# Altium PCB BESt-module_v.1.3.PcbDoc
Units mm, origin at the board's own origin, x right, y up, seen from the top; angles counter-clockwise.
Board outline 26.5 x 50.5 mm, 2 copper layers (Top, Bottom); 61 components, 102 nets, 346 pads, 158 vias.
Unrouted connection lines stored in the file: 17.
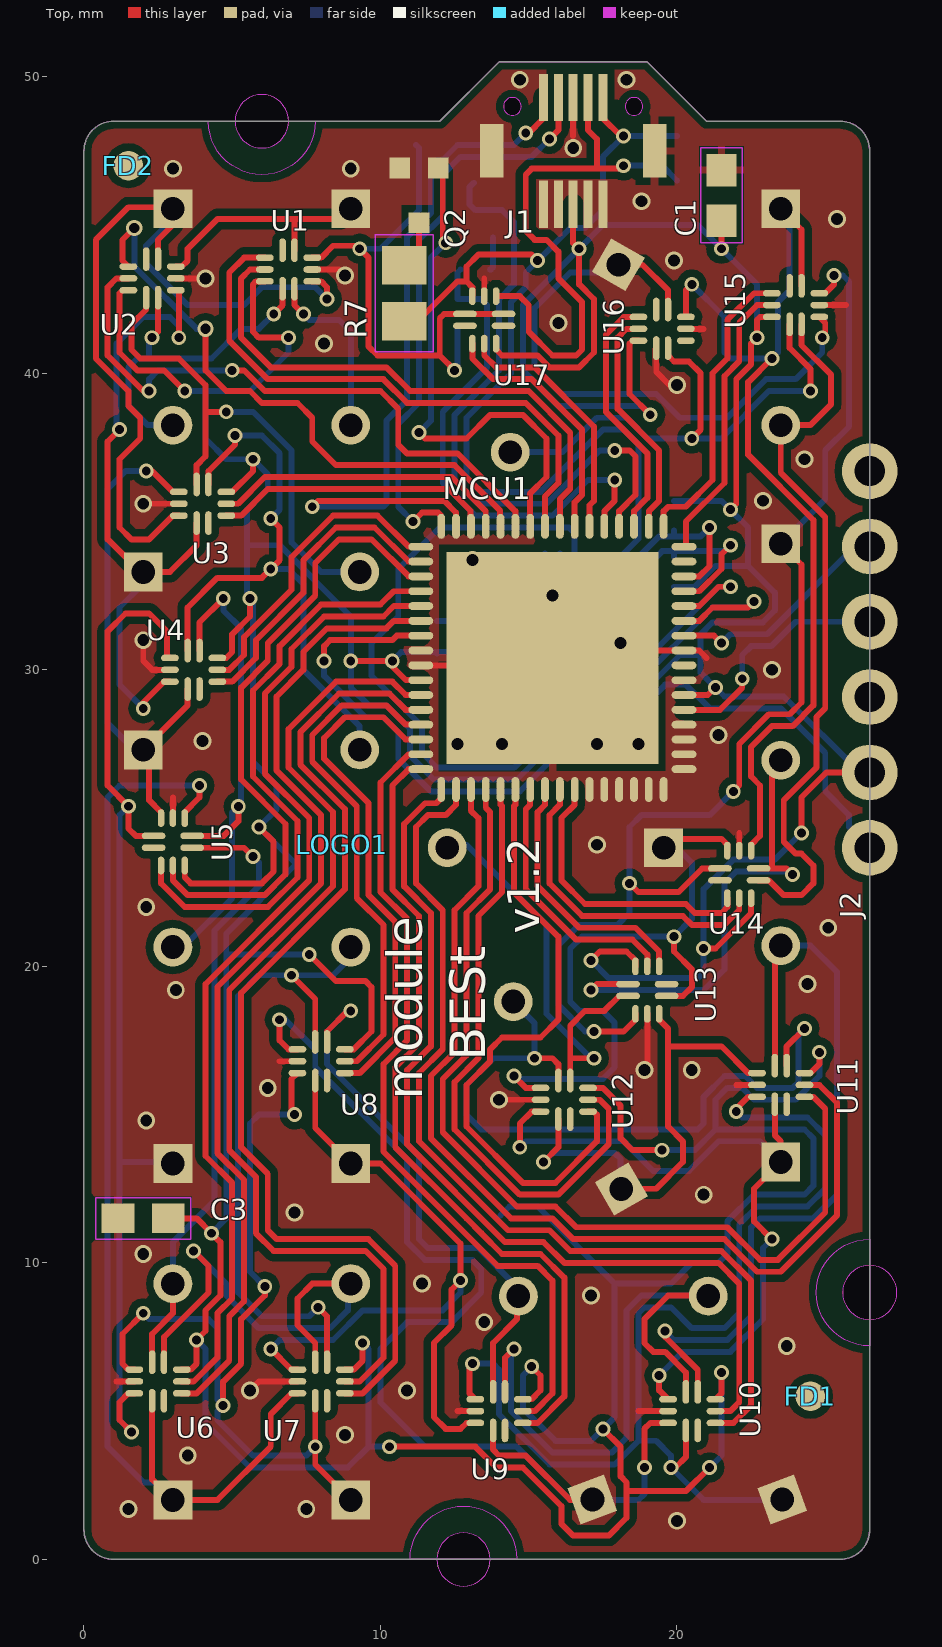
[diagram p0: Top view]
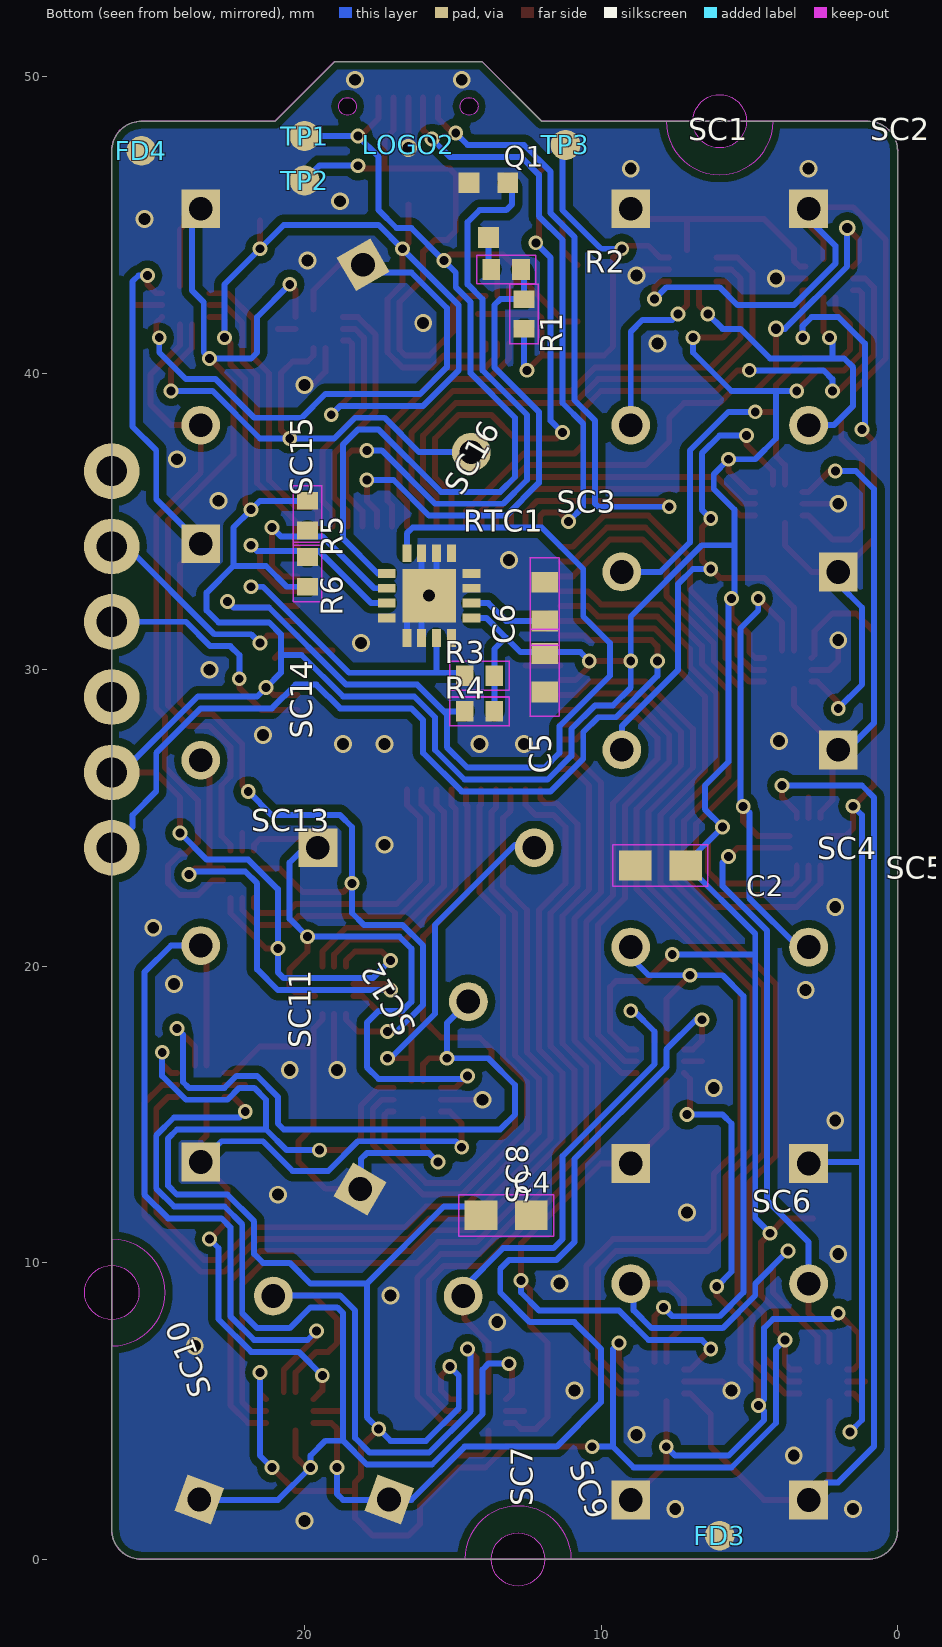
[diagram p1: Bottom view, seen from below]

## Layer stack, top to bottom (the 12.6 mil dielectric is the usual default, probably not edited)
Top Solder: solder mask 0.0102, Solder Resist, Dk 3.5
Top: signal copper 0.035
Dielectric 1: dielectric 0.32, FR-4, Dk 4.8
Bottom: signal copper 0.035
Bottom Solder: solder mask 0.0102, Solder Resist, Dk 3.5

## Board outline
19,50.5 21,48.5 25.5,48.5 cw(c25.5,47.5) 26.5,47.5 26.5,1 cw(c25.5,1) 25.5,0 1,0 cw(c1,1) 0,1 0,47.5 cw(c1,47.5) 1,48.5 12,48.5 14,50.5
cut-out: 26.5,8.085 ccw(c26.5,9) 27.415,9 ccw(c26.5,9) 26.5,9.915 ccw(c26.5,9) 25.585,9 ccw(c26.5,9)
cut-out: 12.8,-0.9 ccw(c12.8,0) 13.7,0 ccw(c12.8,0) 12.8,0.9 ccw(c12.8,0) 11.9,0 ccw(c12.8,0)
cut-out: 6,47.6 ccw(c6,48.5) 6.9,48.5 ccw(c6,48.5) 6,49.4 ccw(c6,48.5) 5.1,48.5 ccw(c6,48.5)
cut-out: 18.55,48.7 ccw(c18.55,49) 18.85,49 ccw(c18.55,49) 18.55,49.3 ccw(c18.55,49) 18.25,49 ccw(c18.55,49)
cut-out: 14.45,48.7 ccw(c14.45,49) 14.75,49 ccw(c14.45,49) 14.45,49.3 ccw(c14.45,49) 14.15,49 ccw(c14.45,49)

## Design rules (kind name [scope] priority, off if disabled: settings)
BoardOutlineClearance mdCopperDimension [All] p1: gap=0.254 ignorepadtopadclearanceinfootprint=FALSE except(0: Arc-SplitContinuation Track-SplitContinuation SMDPad-SplitContinuation THPad-SplitContinuation Via-SplitContinuation Fill-SplitContinuation Poly-SplitContinuation Region-SplitContinuation Text-SplitContinuation; 0.152: Poly-OutlineEdge Poly-CavityEdge Poly-CutoutEdge Poly-SplitBarrior)
Clearance Clearance_for_PolygonClass_Isolate_10 [InPolygonClass('Isolate_10') vs IsArc Or IsTrack Or IsPad Or IsVia Or IsFill Or IsRegion Or IsText] p1: gap=0.254 ignorepadtopadclearanceinfootprint=FALSE
Clearance "Clearance (Same Net)" [All] p2: gap=0.152 ignorepadtopadclearanceinfootprint=FALSE
Clearance [All] p3: gap=0.152 ignorepadtopadclearanceinfootprint=FALSE
HoleSize [All] p1: absolutevalues=TRUE maxlimit=2540 minlimit=0.3 maxpercent=80.000 minpercent=20.000
HoleToHoleClearance mdDrill [All] p1: gap=0.152 allowstackedmicrovias=TRUE
MinimumSolderMaskSliver [All] p1 off: minsoldermaskwidth=0.254
PasteMaskExpansion Expansion_SMDPaste_OFF [InPadClass('SMDPaste_OFF')] p1: expansion=0
PasteMaskExpansion mlMinCreamFrame [All] p2: expansion=0
PolygonConnect PolygonConnect_For_PolygonThermal_ON_Width100000_Gap100000 [InPolygonClass('PolygonThermal_ON_Width100000_Gap100000') vs Not IsVia] p1: connectstyle=Relief reliefconductorwidth=0.254 reliefentries=4 polygonreliefangle="90 Angle" airgapwidth=0.254
PolygonConnect ThermalVias [IsVia] p2: connectstyle=Direct reliefconductorwidth=0.254 reliefentries=4 polygonreliefangle="90 Angle" airgapwidth=0.254
PolygonConnect [All] p3: connectstyle=Relief reliefconductorwidth=0.254 reliefentries=4 polygonreliefangle="90 Angle" airgapwidth=0.254
RoutingVias [All] p1: holewidth=0.3 width=0.5 viastyle="Through Hole" minholewidth=0.3 minwidth=0.5 maxholewidth=2.54 maxwidth=2.54
SolderMaskExpansion mlMinStopFrame [All] p1: expansion=0.102 istentingtop=FALSE
Width [All] p1: maxlimit=0.254 minlimit=0.152 preferedwidth=0.152
26 further rules are at their usual default settings.

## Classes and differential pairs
polygon class PolygonThermal_ON_Width100000_Gap100000: Polygon_1_Net_GND Polygon_2_Net_GND
polygon class Isolate_10: Polygon_1_Net_GND Polygon_2_Net_GND
pad class SMDPaste_OFF: FD1-1 FD2-1 FD3-1 FD4-1 TP1-P$1 TP2-P$1 TP3-P$1

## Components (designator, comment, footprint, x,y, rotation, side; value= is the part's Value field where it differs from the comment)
C1 "" 0603 21.5,46 r270 top
C2 "" 0603 8,23.4 r180 bottom
C3 "" 0603 2,11.5 r0 top
C4 "" 0603 13.2,11.6 r0 bottom
C5 "" C0402 11.9,29.9 r270 bottom
C6 "" C0402 11.9,32.3 r90 bottom
FD1 "" FIDUCIAL-1X2 24.5,5.5 r0 top
FD2 "" FIDUCIAL-1X2 1.5,47 r0 top
FD3 "" FIDUCIAL-1X2 6,0.8 r180 bottom
FD4 "" FIDUCIAL-1X2 25.5,47.5 r180 bottom
J1 "" 10132797-10POS-PLUG 16.5,47.5 r0 top
J2 "" 1X06_NO_SILK 26.5,24 r90 top
LOGO1 "" IIOT 8.7,24.1 r90 top
LOGO2 "" IIOT 16.5,47.7 r90 bottom
MCU1 "" QFN50P900X900X100-65T715N 15.8,30.4 r0 top
Q1 "" SOT323 13.8,45.5 r0 bottom
Q2 "" SOT323 11.3,46 r180 top
R1 "" R0402 12.6,42 r270 bottom
R2 "" R0402 13.2,43.5 r180 bottom
R3 "" R0402 14.1,29.8 r0 bottom
R4 "" R0402 14.1,28.6 r0 bottom
R5 "" R0402 19.9,35.2 r270 bottom
R6 "" R0402 19.9,33.3 r90 bottom
R7 "" R0805 10.8,42.7 r270 top
RTC1 "" QFN-16-3X3 15.8,32.5 r270 bottom
SC1 "" EATON-13X11.3X6-V 9,41.9 r0 bottom
SC2 "" EATON-13X11.3X6-V 3,41.9 r0 bottom
SC3 "" EATON-13X11.3X6-V 5.65,33.3 r90 bottom
SC4 "" EATON-13X11.3X6-V 5.65,27.3 r90 bottom
SC5 "" EATON-13X11.3X6-V 3,17 r180 bottom
SC6 "" EATON-13X11.3X6-V 3,5.65 r180 bottom
SC7 "" EATON-13X11.3X6-V 9,5.65 r180 bottom
SC8 "" EATON-13X11.3X6-V 9,17 r180 bottom
SC9 "" EATON-13X11.3X6-V 15.9,5.45 r200 bottom
SC10 "" EATON-13X11.3X6-V 22.3,5.45 r200 bottom
SC11 "" EATON-13X11.3X6-V 23.5,17.05 r180 bottom
SC12 "" EATON-13X11.3X6-V 16.3,15.65 r210 bottom
SC13 "" EATON-13X11.3X6-V 15.9,24 r270 bottom
SC14 "" EATON-13X11.3X6-V 23.5,30.6 r0 bottom
SC15 "" EATON-13X11.3X6-V 23.5,41.9 r0 bottom
SC16 "" EATON-13X11.3X6-V 16.2,40.5 r330 bottom
TP1 "" PAD.03X.04 20,48 r180 bottom
TP2 "" PAD.03X.04 20,46.5 r180 bottom
TP3 "" PAD.03X.04 11.2,47.7 r180 bottom
U1 "" CP-10-10 6.9,43.5 r270 top
U2 "" CP-10-10 2.3,43.2 r270 top
U3 "" CP-10-10 4,35.6 r90 top
U4 "" CP-10-10 3.7,30 r90 top
U5 "" CP-10-10 3,24.2 r0 top
U6 "" CP-10-10 2.5,6 r90 top
U7 "" CP-10-10 8,6 r90 top
U8 "" CP-10-10 8,16.8 r90 top
U9 "" CP-10-10 14,5 r90 top
U10 "" CP-10-10 20.5,5 r90 top
U11 "" CP-10-10 23.5,16 r90 top
U12 "" CP-10-10 16.2,15.5 r90 top
U13 "" CP-10-10 19,19.2 r180 top
U14 "" CP-10-10 22.1,23.1 r0 top
U15 "" CP-10-10 24,42.3 r270 top
U16 "" CP-10-10 19.5,41.5 r270 top
U17 "" CP-10-10 13.5,41.8 r0 top

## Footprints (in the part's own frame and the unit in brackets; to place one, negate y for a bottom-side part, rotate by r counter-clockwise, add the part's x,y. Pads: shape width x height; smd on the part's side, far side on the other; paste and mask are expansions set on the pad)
1X06_NO_SILK [mil] "1X06_NO_SILK"
  round 74 hole 40: 1(0,0) 2(100,0) 3(200,0) 4(300,0) 5(400,0) 6(500,0)
0603 [mm] "0603"
  rect 1.1x1 smd: 1(-0.85,0) 2(0.85,0)
  Top keep-out lines w0.051: 1.6,-0.7 -1.6,-0.7 -1.6,0.7 1.6,0.7 1.6,-0.7
10132797-10POS-PLUG [mm] "10132797-10POS-PLUG"
  rect 0.3x1.6 smd: 1(1,1.8) 2(0.5,1.8) 3(0,1.8) 4(-0.5,1.8) 5(-1,1.8) 6(-1,-1.8) 7(-0.5,-1.8) 8(0,-1.8) 9(0.5,-1.8) 10(1,-1.8)
  rect 0.8x1.8 smd: MNT1(-2.75,0) MNT2(2.75,0)
C0402 [mm] "C0402"
  rect 0.7x0.9 smd: 1(-0.65,0) 2(0.65,0)
  Top keep-out lines w0.051: 1.473,0.483 1.473,-0.483 -1.473,-0.483 -1.473,0.483 1.473,0.483
CP-10-10 [mil] "CP-10-10"
  rrect100% 8.66x23.62 smd: 1(-15.75,31.5) 4(-15.75,-31.5) 5(0,-31.5) 6(15.75,-31.5) 9(15.75,31.5) 10(0,31.5)
  rrect100% 31.5x8.66 smd: 2(-25.59,7.87) 3(-25.59,-7.87) 7(25.59,-7.87) 8(25.59,7.87)
EATON-13X11.3X6-V [mil] "EATON-13X11.3X6-V"
  round 51.5 hole 31.5: N(0,143.7)
  rect 51.5x51.5 / inner round 47.58 / far side rect 51.5x51.5 hole 31.5: P(0,-143.7)
FIDUCIAL-1X2 [mm] "FIDUCIAL-1X2"
  rrect100% 1x1 smd paste+0: 1(0,0)
IIOT [mm] "IIOT"
PAD.03X.04 [mil] "PAD.03X.04"
  rrect100% 40x40 smd paste+0: P$1(0,0)
QFN50P900X900X100-65T715N [mil] "QFN50P900X900X100-65T715N"
  rrect100% 32.96x10.39 smd: 1(-174.7,147.64) 2(-174.7,127.95) 3(-174.7,108.27) 4(-174.7,88.58) 5(-174.7,68.9) 6(-174.7,49.21) 7(-174.7,29.53) 8(-174.7,9.84) 9(-174.7,-9.84) 10(-174.7,-29.53) 11(-174.7,-49.21) 12(-174.7,-68.9) 13(-174.7,-88.58) 14(-174.7,-108.27) 15(-174.7,-127.95) 16(-174.7,-147.64) 33(174.7,-147.64) 34(174.7,-127.95) 35(174.7,-108.27) 36(174.7,-88.58) 37(174.7,-68.9) 38(174.7,-49.21) 39(174.7,-29.53) 40(174.7,-9.84) 41(174.7,9.84) 42(174.7,29.53) 43(174.7,49.21) 44(174.7,68.9) 45(174.7,88.58) 46(174.7,108.27) 47(174.7,127.95) 48(174.7,147.64)
  rrect100% 10.39x32.96 smd: 17(-147.64,-174.7) 18(-127.95,-174.7) 19(-108.27,-174.7) 20(-88.58,-174.7) 21(-68.9,-174.7) 22(-49.21,-174.7) 23(-29.53,-174.7) 24(-9.84,-174.7) 25(9.84,-174.7) 26(29.53,-174.7) 27(49.21,-174.7) 28(68.9,-174.7) 29(88.58,-174.7) 30(108.27,-174.7) 31(127.95,-174.7) 32(147.64,-174.7) 49(147.64,174.7) 50(127.95,174.7) 51(108.27,174.7) 52(88.58,174.7) 53(68.9,174.7) 54(49.21,174.7) 55(29.53,174.7) 56(9.84,174.7) 57(-9.84,174.7) 58(-29.53,174.7) 59(-49.21,174.7) 60(-68.9,174.7) 61(-88.58,174.7) 62(-108.27,174.7) 63(-127.95,174.7) 64(-147.64,174.7)
  rect 281.5x281.5 smd: 65(0,0)
QFN-16-3X3 [mm] "QFN-16-3X3"
  rect 0.6x0.3 smd: 1(-1.43,0.75) 2(-1.43,0.25) 3(-1.43,-0.25) 4(-1.43,-0.75) 9(1.43,-0.75) 10(1.43,-0.25) 11(1.43,0.25) 12(1.43,0.75)
  rect 0.3x0.6 smd: 5(-0.75,-1.43) 6(-0.25,-1.43) 7(0.25,-1.43) 8(0.75,-1.43) 13(0.75,1.43) 14(0.25,1.43) 15(-0.25,1.43) 16(-0.75,1.43)
  rect 1.8x1.8 smd: EP(0,0)
R0402 [mm] "R0402"
  rect 0.6x0.7 smd: 1(-0.5,0) 2(0.5,0)
  Top keep-out lines w0.051: 1,0.483 1,-0.483 -1,-0.483 -1,0.483 1,0.483
R0805 [mm] "R0805"
  rect 1.3x1.5 smd: 1(-0.95,0) 2(0.95,0)
  Top keep-out lines w0.051: 1.973,-0.983 -1.973,-0.983 -1.973,0.983 1.973,0.983 1.973,-0.983
SOT323 [mm] "SOT323"
  rect 0.7x0.7 smd: 1(-0.65,-0.925) 2(0.65,-0.925) 3(0,0.925)

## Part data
C1 C2 C3 C4: library part 0603
C5 C6: library part C0402
FD1 FD2 FD3 FD4: library part FIDUCIAL-1X2
J1: library part 10132797-10POS-PLUG
J2: library part 1X06_NO_SILK
LOGO1 LOGO2: library part IIOT
MCU1: library part QFN50P900X900X100-65T715N
Q1 Q2: library part SOT323
R1 R2 R3 R4 R5 R6: library part R0402
R7: library part R0805
RTC1: library part QFN-16-3X3
SC1 SC2 SC3 SC4 SC5 SC6 SC7 SC8 SC9 SC10 SC11 SC12 SC13 SC14 SC15 SC16: library part EATON-13X11.3X6-V
TP1 TP2 TP3: library part PAD.03X.04
U1 U2 U3 U4 U5 U6 U7 U8 U9 U10 U11 U12 U13 U14 U15 U16 U17: library part CP-10-10

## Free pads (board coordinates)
  round 1.8 hole 1.8 unplated: MH1(6,48.5) MH3(12.8,0)
  round 0.6 hole 0.6 unplated: MH1(14.45,49) MH2(18.55,49)
  round 1.83 hole 1.83 unplated: MH2(26.5,9)

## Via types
v1: diameter 0.5/0.5 (per signal layer), hole 0.3, Top to Bottom, 105 vias
v2: diameter 0.6/0.6 (per signal layer), hole 0.4, Top to Bottom, 51 vias
v3: diameter 0.55/0.55 (per signal layer), hole 0.35, Top to Bottom, 2 vias

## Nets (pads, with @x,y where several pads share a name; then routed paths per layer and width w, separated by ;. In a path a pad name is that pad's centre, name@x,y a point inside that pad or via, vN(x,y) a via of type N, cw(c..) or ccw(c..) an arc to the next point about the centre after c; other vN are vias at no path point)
ADC: MCU1.53 R1.1 R2.2 | length 17.2
  Top w0.2: MCU1.53@17.55,34.837 17.55,35.35 17.9,35.7 v1(17.9,36.4)
  Bottom w0.2: R2.2 12.6,43.4 R1.1 13.4,42.5 13.6,42.3 13.6,40.198 12.1,38.698 12.1,36.303 13.203,35.2 15.8,35.2 17,36.4 v1(17.9,36.4)
C1-N: SC1.N U1.8 | length 6
  Top w0.2: U1.8 7.1,42.3 v1(7.4,42)
  Bottom w0.2: v1(7.4,42) 7.6,41.8 8.6,41.8 9,41.4 SC1.N
C1-N-SW: MCU1.56 U1.5 | length 18.7
  Top w0.2: U1.5 5.6,43.5 5.3,43.2 5.3,41.2 6.3,40.2 10.2,40.2 11,39.4 15,39.4 16.4,38 16.4,36.102 16.05,35.752 MCU1.56
C1-NC: U1.3
C1-P: SC1.P U1.2 U2.1 | length 8
  Top w0.2: U2.1 3.3,43.6 3.5,43.8 3.5,44.2 4.5,45.2 7.1,45.2 ; U1.2 7.1,45.2 ; SC1.P 8.65,45.2 7.1,45.2
C1-P-SW: MCU1.57 U1.4 | length 19.4
  Top w0.2: U1.4 5.402,43.9 4.9,43.398 4.9,41.1 6.2,39.8 10.1,39.8 10.9,39 14.9,39 16,37.9 16,36.3 15.55,35.85 MCU1.57
C2-N: SC2.N U1.7 U2.8 | length 11.9
  Top w0.2: v1(2.3,41.2) 2.5,41.4 U2.8 ; v1(6.4,42) 6.7,42.3 U1.7
  Bottom w0.2: v1(2.3,41.2) 2.2,41.1 2.2,40.5 ; SC2.N 2.15,38.25 1.5,38.9 1.5,40.2 1.8,40.5 2.2,40.5 ; v1(6.4,42) 5.9,41.5 5.3,41.5 4.3,40.5 2.2,40.5
C2-N-SW: MCU1.59 U2.5 | length 21.1
  Top w0.2: U2.5@1.5,43.2 1.1,43.2 0.8,42.9 0.8,40.6 2,39.4 v1(2.2,39.4) ; v1(5,40.1) 5.4,40.1 6.1,39.4 10,39.4 10.6,38.8 10.6,37.589 10.889,37.3 12.6,37.3 14.55,35.35 MCU1.59
  Bottom w0.2: v1(2.2,39.4) 2.2,39.8 2.5,40.1 v1(5,40.1)
C2-NC: U2.3
C2-P: SC2.P U1.9 U2.2 U3.1 | length 28.4
  Top w0.2: U2.2 2.5,44.5 3,45 SC2.P 3,45.6 1.5,45.6 0.4,44.5 0.4,40.5 1.5,39.4 1.5,38.9 1.9,38.5 1.9,37.8 1.2,37.1 1.2,34.8 1.6,34.4 2.2,34.4 3,35.2 U3.1 ; U1.9 8,43.1 8.2,42.9 v1(8.2,42.5)
  Bottom w0.2: SC2.P 3,45.2 2.1,44.3 2.1,43.698 3.498,42.3 5.4,42.3 6,42.9 7.8,42.9 v1(8.2,42.5)
C2-P-SW: MCU1.60 U2.4 | length 20.4
  Top w0.2: U2.4@1.5,43.6 1.3,43.8 1.3,44.5 v3(1.7,44.9) ; v3(4.1,41.5) 4.1,40.1 4.8,39.4 5.6,39.4 ; 5.602,39.4 5.6,39.4 ; MCU1.60 14.035,34.853 14.035,35.364 12.498,36.9 8.5,36.9 7.7,37.7 7.7,38.5 7.2,39 6,39 5.6,39.4
  Bottom w0.2: v3(1.7,44.9) 1.7,43.6 3.8,41.5 v3(4.1,41.5)
C3-N: SC3.N U2.7 U3.8 | length 17.7
  Top w0.2: U2.7 2.1,42.15 1.6,41.65 1.6,40.8 1.9,40.5 3.2,40.5 4.1,39.6 4.1,38.7 ; U3.8 3.8,36.9 4.1,37.2 4.1,38.7 ; v1(4.8,38.7) 4.1,38.7
  Bottom w0.2: v1(4.8,38.7) 5.7,38.7 7,37.4 7,34.3 8,33.3 SC3.N
C3-N-SW: MCU1.61 U3.5 | length 10.1
  Top w0.2: U3.5 5.2,35.6 6.1,36.5 12.4,36.5 13.55,35.35 MCU1.61
C3-NC: U3.3
C3-P: SC3.P U2.9 U3.2 U4.1 | length 22.7
  Top w0.2: v1(1.2,38.1) 0.8,37.7 0.8,34.4 1.9,33.3 SC3.P 2.9,33.3 3.8,34.2 U3.2 ; v1(2,28.7) 2,28.9 2.7,29.6 U4.1 ; U2.9 3.2,42.8 v1(3.2,41.2)
  Bottom w0.2: v1(1.2,38.1) 1.1,38.2 1.1,41 2,41.9 2.9,41.9 3.2,41.6 v1(3.2,41.2) ; v1(2,28.7) 1.2,29.5 1.2,32.1 2,32.9 SC3.P
C3-P-SW: MCU1.62 U3.4 | length 9.4
  Top w0.2: U3.4 5.3,35.2 6.2,36.1 12.298,36.1 13.035,35.364 13.035,34.853 MCU1.62
C4-N: SC4.N U3.7 U4.8 | length 20.5
  Top w0.2: U4.8 3.5,32.1 4.5,33.1 6,33.1 v1(6.3,33.4) 6.6,33.7 6.6,34.8 v1(6.3,35.1) ; U3.7 4.2,36.7 5.1,37.6 v1(5.1,37.9)
  Bottom w0.2: v1(5.1,37.9) 6,37.9 6.6,37.3 6.6,35.4 v1(6.3,35.1) ; v1(6.3,33.4) 6.9,33.4 7.4,32.9 7.4,30 9.3,28.1 SC4.N
C4-N-SW: MCU1.1 U4.5 | length 10.4
  Top w0.2: U4.5 4.9,30 5.4,30.5 5.4,31.1 7,32.7 7,33.8 8.4,35.2 9.9,35.2 10.95,34.15 MCU1.1
C4-NC: U4.3
C4-P: SC4.P U3.9 U4.2 U5.1 | length 17.6
  Top w0.2: v1(2.1,36.7) 2.3,36.7 3,36 U3.9 ; U5.1@2.6,25 2.6,25.2 2.2,25.6 2.2,27.1 SC4.P 3.5,28.8 U4.2
  Bottom w0.2: SC4.P 1.7,27.3 0.8,28.2 0.8,36.1 1.4,36.7 v1(2.1,36.7)
C4-P-SW: MCU1.2 U4.4 | length 10.5
  Top w0.2: U4.4 5,29.6 5.8,30.4 5.8,31 5.802,31 7.4,32.598 7.4,33.698 8.502,34.8 9.8,34.8 10.95,33.65 MCU1.2
C5-N: SC5.N U4.7 U5.8 | length 17.5
  Top w0.2: U5.8 4.715,24.4 5.207,24.893 v1(5.207,25.393) ; U4.7 3.9,31.6 v1(4.7,32.4)
  Bottom w0.2: SC5.N 3.35,20.65 5,22.3 5,25.185 v1(5.207,25.393) 5.3,25.485 5.3,31.4 4.7,32 v1(4.7,32.4)
C5-N-SW: MCU1.3 U5.5 | length 21.4
  Top w0.2: U5.5 3,22.902 3.502,22.4 6.1,22.4 6.8,23.1 6.8,24.8 5.3,26.3 5.3,29.4 6.2,30.3 6.2,30.9 7.8,32.5 7.8,33.6 8.6,34.4 9.7,34.4 10.95,33.15 MCU1.3
C5-NC: U5.3
C5-P: SC5.P U4.9 U5.2 U6.1 | length 36.3
  Top w0.2: v1(1.6,4.3) 1.2,4.7 1.2,5.3 1.5,5.6 U6.1 ; U5.2 1.75,24.4 1.5,24.65 v1(1.5,25.4) 0.8,26.1 0.8,31.3 1.4,31.9 2.2,31.9 2.8,31.3 2.8,30.5 U4.9
  Bottom w0.2: v1(1.5,25.4) 1.2,25.1 1.2,13.4 ; v1(1.6,4.3) 1.2,4.7 1.2,13.4 ; SC5.P 2.95,13.4 1.2,13.4
C5-P-SW: MCU1.4 U5.4 | length 20.3
  Top w0.2: U5.4 2.6,22.8 3.4,22 6.202,22 7.2,22.998 7.2,24.9 5.7,26.4 5.7,29.3 6.6,30.2 6.6,30.8 8,32.2 9.998,32.2 10.448,32.65 MCU1.4
C6-N: SC6.N U5.7 U6.8 | length 20.8
  Top w0.2: U6.8 2.3,7.6 3,8.3 SC6.N ; U5.7 5.4,24 v1(5.7,23.7)
  Bottom w0.2: SC6.N 3,10.7 4.4,12.1 4.4,21.2 5.9,22.7 5.9,23.5 v1(5.7,23.7)
C6-N-SW: MCU1.5 U6.5 | length 33.4
  Top w0.2: U6.5 3.7,6 4.5,6.8 4.5,8.3 5,8.8 5,12.702 4.1,13.602 4.1,19.4 7.6,22.9 7.6,25 6.1,26.5 6.1,29.2 7,30.1 7,30.7 8.1,31.8 10.1,31.8 10.45,32.15 MCU1.5
C6-NC: U6.3
C6-P: SC6.P U5.9 U6.2 U7.1 | length 39.4
  Top w0.2: U6.2 2.3,2.7 SC6.P 4.5,2 6.3,3.8 6.3,4.9 7,5.6 U7.1 ; U5.9@3.4,25 3.4,25.2 3.9,25.7 v1(3.9,26.1)
  Bottom w0.2: SC6.P 2.4,2.6 2,2.6 0.8,3.8 0.8,25.7 1.2,26.1 v1(3.9,26.1)
C6-P-SW: MCU1.6 U6.4 | length 33.4
  Top w0.2: U6.4 3.8,5.6 4.9,6.7 4.9,8.2 5.4,8.7 5.4,12.8 4.5,13.7 4.5,19.302 8,22.802 8,25.1 6.5,26.6 6.5,29.1 7.4,30 7.4,30.602 8.198,31.4 10.2,31.4 10.45,31.65 MCU1.6
C7-N: SC7.N U6.7 U7.8 | length 16.7
  Top w0.2: U6.7 2.7,7.497 4.2,8.997 4.2,9.9 v1(3.7,10.4) ; U7.8 7.8,7.3 7.2,7.9 7.2,8.8 7.7,9.3 SC7.N
  Bottom w0.2: v1(3.7,10.4) 4.8,9.3 4.8,8.9 5.9,7.8 8.3,7.8 8.9,8.4 8.9,9.2 SC7.N
C7-N-SW: MCU1.11 U7.5 | length 34.2
  Top w0.2: U7.5 9.3,6 10.1,6.8 10.1,9.8 9.5,10.4 6.4,10.4 5.8,11 5.8,12.9 4.9,13.8 4.9,19.2 8.4,22.7 8.4,25.205 6.9,26.705 6.9,28 8.5,29.6 10.4,29.6 10.85,29.15 MCU1.11
C7-NC: U7.3
C7-P: SC7.P U6.9 U7.2 U8.1 | length 29.7
  Top w0.2: U6.9 1.5,6.4 1.3,6.6 1.3,7.6 v1(2,8.3) ; v1(4.695,5.195) 4.695,5.995 5.3,6.6 5.3,8.1 6.1,8.9 v1(6.1,9.2) ; v1(7.1,15) 7,15.1 7,16.2 U8.1 ; U7.2 v1(7.8,3.8) 7.8,3.2 SC7.P
  Bottom w0.2: v1(2,8.3) 2.2,8.1 4.202,8.1 4.5,7.802 4.5,5.389 v1(4.695,5.195) 4.5,5 4.5,4.7 5.7,3.5 7.5,3.5 v1(7.8,3.8) ; v1(6.1,9.2) 5.6,9.7 5.6,14.7 5.9,15 v1(7.1,15)
C7-P-SW: MCU1.12 U7.4 | length 34.2
  Top w0.2: U7.4 9.398,5.6 10.5,6.702 10.5,9.898 9.598,10.8 6.5,10.8 6.2,11.1 6.2,13 5.3,13.9 5.3,19.098 8.8,22.598 8.8,25.303 7.3,26.803 7.3,27.898 8.602,29.2 10.3,29.2 10.85,28.65 MCU1.12
C8-N: SC8.N U7.7 U8.8 | length 22.4
  Top w0.2: v1(7,19.7) 7.8,18.9 U8.8 ; v1(7.9,8.5) 8.2,8.2 U7.7
  Bottom w0.2: v1(7.9,8.5) 7.6,8.2 6,8.2 5.2,9 5.2,19 5.9,19.7 v1(7,19.7) 8.4,19.7 9,20.3 SC8.N
C8-N-SW: MCU1.13 U8.5 | length 17.1
  Top w0.2: U8.5 9.2,16.8 10.1,17.7 10.1,21.4 9.2,22.3 9.2,25.402 7.7,26.902 7.7,27.8 8.7,28.8 10.2,28.8 10.85,28.15 MCU1.13
C8-NC: U8.3
C8-P: SC8.P U7.9 U8.2 U9.1 | length 24.8
  Top w0.2: v1(6.3,7.1) 7,6.4 U7.9 ; U8.2 7.8,14.55 SC8.P 10,13.35 12.7,10.65 v1(12.7,9.4) 12.4,9.1 12.4,7.9 11.8,7.3 11.8,4.8 12.2,4.4 12.7,4.4 12.9,4.6 U9.1
  Bottom w0.2: v1(6.3,7.1) 6.6,7.4 8.4,7.4 9.4,8.4 12.1,8.4 12.7,9 v1(12.7,9.4)
C8-P-SW: MCU1.14 U8.4 | length 17.2
  Top w0.2: U8.4 9.298,16.4 10.5,17.602 10.5,21.502 9.6,22.402 9.6,25.5 8.1,27 8.1,27.7 8.8,28.4 10.1,28.4 10.85,27.65 MCU1.14
C9-N: SC9.N U8.7 U9.8 | length 18.7
  Top w0.2: U8.7 8.2,17.8 8.9,18.5 v1(9,18.5) ; U9.8 13.8,7.3 14.6,8.1 14.6,8.828 SC9.N
  Bottom w0.2: v1(9,18.5) 8.9,18.5 8.2,17.8 8.2,16.7 11.3,13.6 11.3,10.8 11.6,10.5 13.3,10.5 14.6,9.2 14.6,8.931 SC9.N
C9-N-SW: MCU1.15 U9.5 | length 27.5
  Top w0.2: MCU1.15 10.95,27.15 10,26.2 10,22.5 10.9,21.6 10.9,17.503 10.1,16.703 10.1,13.748 13.948,9.9 15.3,9.9 15.8,9.4 15.8,5.6 15.2,5 U9.5
C9-NC: U9.3
C9-P: SC9.P U8.9 U9.2 U10.1 | length 38.6
  Top w0.2: v1(6.6,18.2) 6.6,17.5 6.9,17.2 U8.9 ; U9.2 13.8,3.7 14,3.5 14.898,3.5 16.398,2 17.128,2 SC9.P ; v1(18.9,3.1) 18.9,4.4 19.1,4.6 U10.1
  Bottom w0.2: v1(6.6,18.2) 6.8,18.2 7.8,17.2 7.8,16.6 10.9,13.5 10.9,10.7 11.5,10.1 13.1,10.1 13.4,9.8 13.4,9 12.4,8 10.9,8 10,7.1 10,5.3 11.5,3.8 14.6,3.8 16.4,2 17.128,2 SC9.P 17.169,2 18.7,2 18.9,2.2 v1(18.9,3.1)
C9-P-SW: MCU1.16 U9.4 | length 27.4
  Top w0.2: MCU1.16 10.95,26.65 10.4,26.1 10.4,22.6 11.3,21.7 11.3,17.4 10.5,16.6 10.5,13.902 12.9,11.502 12.9,11.5 13.4,11 13.402,11 14.102,10.3 15.4,10.3 16.2,9.5 16.2,5.5 15.3,4.6 U9.4
C10-N: SC10.N U9.7 U10.8 | length 21.4
  Top w0.2: U9.7@14.2,5.65 14.2,6.8 v1(14.5,7.1) ; U10.8 20.3,6.3 19.6,7 19.2,7 18.9,7.3 18.9,8.1 19.7,8.9 21.031,8.9 SC10.N
  Bottom w0.2: v1(14.5,7.1) 14.4,7 14.4,5 15.8,3.6 17.8,3.6 18.3,4.1 18.3,8.4 18.8,8.9 21.031,8.9 SC10.N
C10-N-SW: MCU1.17 U10.5 | length 31.5
  Top w0.2: MCU1.17 12.05,25.663 11.887,25.5 11.5,25.5 10.8,24.8 10.8,22.698 11.7,21.798 11.7,17.302 10.9,16.502 10.9,14 14.2,10.7 15.5,10.7 16.2,10 21.4,10 22.1,9.3 22.1,5.3 21.8,5 U10.5
C10-NC: U10.3
C10-P: SC10.P U9.9 U10.2 U11.1 | length 37.8
  Top w0.2: v1(13.1,6.6) 13,6.5 13,5.6 U9.9 ; v1(19.8,3.1) 19.95,3.1 20.3,3.45 U10.2 ; v1(22,15.1) 22,15.2 22.4,15.6 U11.1
  Bottom w0.2: v1(13.1,6.6) 13.8,6.6 14,6.4 14,4.9 15.7,3.2 17.898,3.2 18.7,4.002 ; v1(22,15.1) 22.2,14.9 24.4,14.9 25,14.3 25,12.502 24.398,11.9 22.7,11.9 22.1,11.3 22.1,8.3 21.6,7.8 20.5,7.8 19.8,8.5 18.898,8.5 18.7,8.302 18.7,4.002 ; SC10.P 23.528,2 20.9,2 v1(19.8,3.1) 19.8,3.5 19.298,4.002 18.7,4.002
C10-P-SW: MCU1.18 U10.4 | length 32.3
  Top w0.2: MCU1.18 12.55,25.45 12.2,25.1 11.6,25.1 11.2,24.7 11.2,22.797 12.1,21.897 12.1,17.203 11.3,16.403 11.3,14.1 14.3,11.1 15.7,11.1 16.4,10.4 21.498,10.4 22.5,9.398 22.5,5.2 21.9,4.6 U10.4
C11-N: SC11.N U10.7 U11.8 | length 26.1
  Top w0.2: v1(19.6,7.7) 19.6,7.5 20.7,6.4 U10.7 ; U11.8 23.3,20.5 SC11.N
  Bottom w0.2: v1(19.6,7.7) 19.9,7.4 21.7,7.4 22.5,8.2 22.5,11.2 22.8,11.5 24.6,11.5 25.4,12.3 25.4,19.8 24.5,20.7 SC11.N
C11-N-SW: MCU1.19 U11.5 | length 34
  Top w0.2: MCU1.19 13.05,25.25 13.3,25 13.3,22.7 12.5,21.9 12.5,17.1 11.7,16.3 11.7,14.2 14.4,11.5 15.798,11.5 16.498,10.8 21.6,10.8 22.7,9.7 23.5,9.7 25.4,11.6 25.4,15.4 24.8,16 U11.5
C11-NC: U11.3
C11-P: SC11.P U10.9 U11.2 U12.1 | length 25
  Top w0.2: v1(14.7,13.9) 14.7,14.7 15.1,15.1 U12.1 ; v1(19.4,6.2) 19.4,5.7 U10.9 ; v1(23.2,10.8) 22.6,11.4 22.6,12.5 SC11.P 23.5,14.1 23.3,14.3 U11.2
  Bottom w0.2: v1(14.7,13.9) 14.9,14.1 18.2,14.1 19.2,13.1 20.4,13.1 21.4,14.1 22.8,14.1 SC11.P ; v1(19.4,6.2) 20.2,7 21.8,7 22.9,8.1 22.9,10.5 v1(23.2,10.8)
C11-P-SW: MCU1.20 U11.4 | length 32
  Top w0.2: MCU1.20 13.55,25.35 13.7,25.2 13.7,22.6 12.9,21.8 12.9,17 12.1,16.2 12.1,14.4 14.6,11.9 15.9,11.9 16.6,11.2 21.7,11.2 22.8,10.1 23.4,10.1 25,11.7 25,15.2 24.6,15.6 U11.4
C12-N: SC12.N U11.7 U12.8 | length 23.6
  Top w0.2: v1(15.2,16.9) 15.8,16.9 16,16.7 U12.8 ; U11.7 23.7,17.3 v1(24.3,17.9)
  Bottom w0.2: SC12.N 15.2,18.086 v1(15.2,16.9) 13.8,16.9 12.9,16 12.9,15 13.4,14.5 20.7,14.5 20.9,14.7 20.9,15.6 21.6,16.3 22.3,16.3 22.7,15.9 23.9,15.9 24.1,16.1 24.1,17.7 v1(24.3,17.9)
C12-N-SW: MCU1.21 U12.5 | length 21
  Top w0.2: MCU1.21 14.05,25.45 14.1,25.4 14.1,22.5 13.3,21.7 13.3,16.902 12.5,16.102 12.5,14.5 14.7,12.3 16,12.3 17.7,14 17.7,15.2 17.4,15.5 U12.5
C12-NC: U12.3
C12-P: SC12.P U11.9 U12.2 U13.1 | length 16.6
  Top w0.2: v1(15.5,13.4) 16,13.9 U12.2 ; SC12.P 18.136,12.5 19.3,12.5 20.2,13.4 20.2,14.098 19.7,14.598 19.7,17.3 ; U13.1 19.4,18.2 19.7,17.9 19.7,17.3 ; U11.9 22.4,16.4 21.5,17.3 19.7,17.3
  Bottom w0.2: v1(15.5,13.4) 15.8,13.7 17.9,13.7 18.1,13.5 18.1,12.514 SC12.P
C12-P-SW: MCU1.22 U12.4 | length 21.1
  Top w0.2: MCU1.22 14.55,25.45 14.5,25.4 14.5,22.5 16,21 16,18.2 15.4,17.6 14.1,17.6 13.7,17.2 13.7,16.8 12.9,16 12.9,14.6 14.8,12.7 15.902,12.7 17.3,14.098 17.3,15 17.2,15.1 U12.4
C13-N: SC13.N U12.7 U13.8 | length 14.7
  Top w0.2: U12.7 16.4,16.9 ; v1(17.2,16.9) 16.4,16.9 ; U13.8 18.05,19 17.55,18.5 16.9,18.5 16.4,18 16.4,16.9
  Bottom w0.2: SC13.N 12.35,24.1 12.9,24.1 15.6,21.4 15.6,18.4 17.1,16.9 v1(17.2,16.9)
C13-N-SW: MCU1.23 U13.5 | length 8.8
  Top w0.2: MCU1.23 15.05,25.45 14.9,25.3 14.9,22.6 16.6,20.9 18.5,20.9 19,20.4 U13.5
C13-NC: U13.3
C13-P: SC13.P U12.9 U13.2 U14.1 | length 22.8
  Top w0.2: v1(14.5,16.3) 14.9,15.9 U12.9 ; SC13.P 19.85,24.3 21.5,24.3 21.7,24.1 U14.1@21.7,23.9 ; U13.2 20.2,19 20.5,19.3 20.5,19.9 19.9,20.5 v1(19.9,21)
  Bottom w0.2: v1(14.5,16.3) 14.6,16.2 17.5,16.2 17.9,16.6 17.9,18.1 17.5,18.5 16.7,18.5 16.4,18.8 16.4,20.6 16.8,21 v1(19.9,21) 20.5,21.6 20.5,23.5 20,24 SC13.P
C13-P-SW: MCU1.24 U13.4 | length 8.9
  Top w0.2: MCU1.24 15.55,25.45 15.3,25.2 15.3,22.7 16.7,21.3 18.6,21.3 19.4,20.5 U13.4
C14-N: SC14.N U13.7 U14.8 | length 16.5
  Top w0.2: v1(17.1,19.2) 17.3,19.4 U13.7 ; U14.8 23.2,23.3 ; SC14.N 23.2,26.65 23.2,23.3 ; v1(23.9,23.1) 23.7,23.3 23.2,23.3
  Bottom w0.2: v1(17.1,19.2) 20.9,19.2 21.6,19.9 21.6,22.8 22,23.2 23.8,23.2 v1(23.9,23.1)
C14-N-SW: MCU1.25 U14.5 | length 10.9
  Top w0.2: MCU1.25 16.05,25.45 15.7,25.1 15.7,22.8 16.8,21.7 20.2,21.7 20.502,21.398 21.598,21.398 22.1,21.9 U14.5
C14-NC: U14.3
C14-P: SC14.P U13.9 U14.2 U15.1 | length 39.9
  Top w0.2: v1(17.2,17.8) 18.2,17.8 18.6,18.2 U13.9 ; v1(18.4,22.8) 18.7,22.5 20.05,22.5 20.85,23.3 U14.2 ; v1(21.9,25.9) 22.1,26.1 22.1,27.5 23.1,28.5 23.8,28.5 24.2,28.9 24.2,33.55 SC14.P ; U15.1 25,42.7 25.3,43 v1(25.3,43.3)
  Bottom w0.2: v1(17.2,17.8) 16.9,17.8 16,18.7 16,20.7 16.7,21.4 18,21.4 18.4,21.8 v1(18.4,22.8) 18.4,24.7 18.8,25.1 21.1,25.1 v1(21.9,25.9) ; SC14.P 25,35.75 25,37.4 25.8,38.2 25.8,43.1 25.6,43.3 v1(25.3,43.3)
C14-P-SW: MCU1.26 U14.4 | length 9.7
  Top w0.2: MCU1.26 16.55,25.45 16.1,25 16.1,22.898 16.898,22.1 20.3,22.1 20.6,21.8 21.5,21.8 21.7,22 U14.4
C15-N: SC15.N U14.7 U15.8 | length 24.5
  Top w0.2: U14.7 23.1,22.9 23.6,22.4 24.2,22.4 24.6,22.8 24.6,23.4 24.2,23.8 24,23.8 23.6,24.2 23.6,25.6 24.7,26.7 24.7,28.4 25,28.7 25,35.15 23.5,36.65 SC15.N 24.5,38.25 25.2,38.95 25.2,39.95 24.2,40.95 U15.8
C15-N-SW: MCU1.48 U15.5 | length 9.7
  Top w0.2: MCU1.48@20.237,34.15 20.3,34.213 20.3,35 21.6,36.3 21.6,39.903 22.1,40.403 22.1,41.7 22.7,42.3 U15.5
C15-NC: U15.3
C15-P: SC15.P U14.9 U15.2 U16.1 | length 33.3
  Top w0.2: U16.1 20.3,42.8 v1(20.5,43) ; U14.9@22.5,23.9 22.5,24.1 22.8,24.4 22.8,26.1 22.5,26.4 22.5,27.4 23.2,28.1 23.9,28.1 24.6,28.8 24.6,35.052 22.4,37.252 22.4,39.7 v1(23.2,40.5) ; SC15.P 24.2,44.85 U15.2
  Bottom w0.2: v1(20.5,43) 21.6,41.9 21.6,40.7 21.8,40.5 v1(23.2,40.5) 23.4,40.7 23.4,42.4 23.8,42.8 23.8,45.25 SC15.P
C15-P-SW: MCU1.49 U15.4 | length 10.1
  Top w0.2: MCU1.49 19.55,35.35 19.7,35.5 20.3,35.5 21.2,36.4 21.2,40.001 21.7,40.501 21.7,41.8 22.6,42.7 U15.4
C16-N: SC16.N U15.7 U16.8 | length 18
  Top w0.2: U16.8 19.7,40.6 19.9,40.4 20.4,40.4 20.8,40 20.8,38.1 v1(20.5,37.8) ; U15.7 23.8,40.85 24.5,40.15 v1(24.5,39.4)
  Bottom w0.2: SC16.N@14.375,37.339 16.139,37.339 17.3,38.5 18.3,38.5 19,37.8 v1(20.5,37.8) 21.5,37.8 23.1,39.4 v1(24.5,39.4)
C16-N-SW: MCU1.50 U16.5 | length 7.9
  Top w0.2: U16.5 18.3,41.5 18,41.2 18,38.798 19.4,37.398 19.4,35.7 19.05,35.35 MCU1.50
C16-NC: U16.3
C16-P: SC16.P U15.9 U16.2 | length 20.8
  Top w0.2: SC16.P 18.839,43.661 19.7,42.8 U16.2 ; U15.9 25,41.7 25,41.3 v1(24.9,41.2)
  Bottom w0.2: SC16.P 17.764,43.4 16.4,43.4 15.2,42.2 15.2,40.2 16.1,39.3 19.298,39.3 20.098,38.5 21.7,38.5 23,39.8 24,39.8 24.9,40.7 v1(24.9,41.2)
C16-P-SW: MCU1.51 U16.4 | length 8.6
  Top w0.2: MCU1.51 18.55,35.35 19,35.8 19,37.3 17.6,38.7 17.6,41.3 18.2,41.9 U16.4
GND: C1.1 C2.1 C3.1 C4.1 C5.2 C6.2 J1.3 J1.MNT1 J1.MNT2 J2.3 MCU1.9 MCU1.41 MCU1.65 Q1.2 Q2.2 RTC1.2 RTC1.3 RTC1.9 RTC1.10 RTC1.EP U1.10 U2.10 U3.10 U4.10 U5.10 U6.10 U7.10 U8.10 U9.10 U10.10 U11.10 U12.10 U13.10 U14.10 U15.10 U16.7 U16.10 U17.10 | length 29.6
  Top w0.2: 1.1,6 U6.10 ; v2(2,31) 2,30.3 2.3,30 U4.10 ; v2(2,35.6) U3.10 ; U5.10@3,25 3,25.7 ; U2.10 v2(4.1,43.2) ; v2(5.6,5.7) 5.9,6 5.9,5.998 6.308,5.998 6.311,6 U7.10 ; 6.6,16.8 U8.10 ; U1.10 8.6,43.5 v2(8.8,43.3) ; MCU1.9 MCU1.65@12.55,30.15 ; 12.6,5 U9.10 ; U17.10 13.5,43.2 ; v2(14,15.5) U12.10 ; 16.5,48 J1.3@16.5,49.3 ; 18.7,5 U10.10 ; v2(18.9,16.5) 19,16.6 U13.10 ; MCU1.65@19.05,30.65 20.237,30.65 20.75,30.65 21,30.4 ; U16.7 19.3,40.05 19.75,39.6 v2(20,39.6) ; U16.10 20.9,41.5 ; 22,16 U11.10 ; U14.10@22.1,23.9 22.1,24.5 ; U15.10 25.7,42.3
  Bottom w0.2: RTC1.2 15.55,32.75 v2(15.8,32.5) ; RTC1.10 16.05,32.25 v2(15.8,32.5) ; RTC1.3 16.05,32.75 v2(15.8,32.5) ; RTC1.9 16.55,31.75 v2(15.8,32.5)
  other v2: 20,1.3 1.5,1.7 7.5,1.7 3.5,3.5 8.8,4.2 10.9,5.7 23.7,7.2 13.5,8 17.1,8.9 11.4,9.3 2,10.3 7.1,11.7 20.9,12.3 2.1,14.8 6.2,15.9 20.5,16.5 3.1,19.2 24.4,19.4 25.1,21.3 2.1,22 17.3,24.1 12.6,27.5 14.1,27.5 17.3,27.5 18.7,27.5 4,27.6 21.4,27.8 23.2,30 18.1,30.9 13.1,33.7 22.9,35.7 24.3,37.1 8.1,41 16,41.7 19.9,43.8 25.4,45.2 18.8,45.8 3,46.9 9,46.9 16.5,47.6 14.7,49.9 18.3,49.9
ICSPCLK: J2.5 MCU1.42 | length 7.7
  Top w0.2: MCU1.42@20.237,31.15 21.25,31.15 v1(21.5,30.9)
  Bottom w0.2: v1(21.5,30.9) 21.8,31.2 23.04,31.2 26,34.16 J2.5
ICSPDAT: J2.4 MCU1.37 | length 8.1
  Top w0.2: MCU1.37@20.237,28.65 21.45,28.65 22.2,29.4 v1(22.2,29.7)
  Bottom w0.2: v1(22.2,29.7) 22.2,30.5 22.5,30.8 23.18,30.8 24,31.62 J2.4
LOAD-CTRL: MCU1.58 Q2.1 | length 17.6
  Top w0.2: v1(11.3,38) 11.5,37.8 12.9,37.8 13.7,38.6 14.8,38.6 15.6,37.8 15.6,36.5 15.05,35.95 MCU1.58 ; Q2.1 12.1,46.775 12.1,44.5 v1(12.2,44.4)
  Bottom w0.2: v1(11.3,38) 11.7,38.4 11.7,43.9 v1(12.2,44.4)
LOAD-S: Q2.3 R7.1 | length 1.6
  Top w0.2: R7.1 11.3,44.15 Q2.3
MCLR: J2.1 MCU1.7 | length 30.4
  Top w0.2: v1(8.1,30.3) 8.1,30.8 8.3,31 10.4,31 10.55,31.15 MCU1.7
  Bottom w0.2: v1(8.1,30.3) 8.1,29.798 9.498,28.4 10.1,28.4 10.6,27.9 10.6,27 11.7,25.9 14.704,25.9 16,27.196 16,28.3 16.4,28.7 18.8,28.7 19.6,29.5 20.3,29.5 21.1,28.7 23.5,28.7 25,27.2 25,25.9 25.8,25.1 25.8,24.7 J2.1
Q1-D: Q1.3 R2.1 | length 1.1
  Bottom w0.2: R2.1 13.725,43.5 13.8,43.575 Q1.3
RTC-AF: C6.1 RTC1.14 | length 2.7
  Bottom w0.2: C6.1 13.2,31.65 13.8,32.25 RTC1.14
RTC-INT1: MCU1.44 R3.2 RTC1.11 | length 11.4
  Top w0.2: MCU1.44@20.237,32.15 20.75,32.15 21.4,32.8 v1(21.8,32.8)
  Bottom w0.2: R3.2 14.7,29.9 15.548,29.9 ; RTC1.11 15.548,31.068 15.548,29.9 ; v1(21.8,32.8) 21.4,32.8 18.5,29.9 15.548,29.9
RTC-INT2: MCU1.43 R4.2 RTC1.4 | length 32.3
  Top w0.2: MCU1.43@20.237,31.65 20.75,31.65 21.2,32.1 22.4,32.1 v1(22.6,32.3)
  Bottom w0.2: R4.2 15.3,28.6 ; RTC1.4 16.55,34.6 16.35,34.8 12,34.8 10.6,33.4 10.6,31.8 9.7,30.9 9.7,29.8 11.4,28.1 11.4,27.198 11.898,26.7 14.507,26.7 15.2,27.393 15.2,28.5 15.3,28.6 ; v1(22.6,32.3) 22.4,32.1 21.198,32.1 18.598,29.5 16.2,29.5 15.3,28.6
RTC-SCL: MCU1.45 R6.2 RTC1.7 | length 8.1
  Top w0.2: MCU1.45@20.237,32.65 20.748,32.65 21.5,33.402 21.5,33.9 v1(21.8,34.2)
  Bottom w0.2: RTC1.7 17.75,32.25 19.5,34 R6.2@19.9,34 ; R6.2 R6.2@19.9,34 ; v1(21.8,34.2) 21.6,34 R6.2@19.9,34
RTC-SDA: MCU1.46 R5.2 RTC1.6 | length 7.2
  Top w0.2: MCU1.46@20.237,33.15 20.75,33.15 21.1,33.5 v1(21.1,34.8)
  Bottom w0.2: RTC1.6 17.65,32.75 19.4,34.5 R5.2@19.9,34.5 ; R5.2 R5.2@19.9,34.5 ; v1(21.1,34.8) 20.8,34.5 R5.2@19.9,34.5
RX5: J1.5 MCU1.63 | length 25.2
  Top w0.2: v1(7.7,35.5) 7.9,35.7 12.15,35.7 12.55,35.3 MCU1.63 ; v1(14.9,48.1) 15,48.1 15.5,48.6 J1.5@15.5,49.3
  Bottom w0.2: v1(7.7,35.5) 10.1,35.5 10.2,35.6 10.2,38.4 10.9,39.1 10.9,44.6 11.7,45.4 11.7,46.8 12.6,47.7 14.5,47.7 v1(14.9,48.1)
SW-GND: MCU1.52 Q1.1 | length 21.9
  Top w0.2: v1(17.9,37.4) 18.4,37.4 18.6,37.2 18.6,35.898 18.05,35.348 MCU1.52
  Bottom w0.2: Q1.1 13,46.275 13,45.7 13.2,45.5 14.1,45.5 14.5,45.1 14.5,43 14,42.5 14,40.1 12.5,38.6 12.5,36.402 13.302,35.6 15.6,35.6 17.4,37.4 v1(17.9,37.4)
TX5: J1.4 MCU1.64 | length 19.6
  Top w0.2: v1(11.1,35) 11.4,35.3 11.95,35.3 12.05,35.2 MCU1.64 ; v1(15.7,47.9) 16,48.2 J1.4@16,49.3
  Bottom w0.2: v1(11.1,35) 10.6,35.5 10.6,38.3 11.3,39 11.3,44.5 12.1,45.3 12.1,46.7 12.7,47.3 15.1,47.3 v1(15.7,47.9)
V-ARY: R1.2 TP3.P$1 U1.1 U17.2 U17.8 | length 18.1
  Top w0.2: U1.1 8,43.9 8.4,44.3 9.2,44.3 v1(9.3,44.2) 9.6,43.9 9.6,40.9 9.9,40.6 12,40.6 ; v1(12.5,40.1) 12,40.6 ; U17.8 U17.2 12.15,42 12,41.85 12,40.6
  Bottom w0.2: v1(9.3,44.2) 10,44.2 11.3,45.5 11.3,47.6 TP3.P$1 ; v1(12.5,40.1) 12.6,40.2 R1.2@12.6,41.5
V-EH: J1.2 TP2.P$1 U17.9 | length 19.2
  Top w0.2: U17.9 14.7,42.6 15,42.3 15,41.4 15.8,40.6 16.6,40.6 16.8,40.8 16.8,42.4 16,43.2 16,44.1 15.6,44.5 15.198,44.5 14.9,44.798 14.9,46.7 15.1,46.9 17.3,46.9 ; J1.2@17,49.3 17,48.2 17.3,47.9 17.3,46.9 ; v1(18.2,47) 18.1,46.9 17.3,46.9
  Bottom w0.2: v1(18.2,47) 19.5,47 TP2.P$1
V-SYS: J1.1 R7.2 RTC1.5 TP1.P$1 U17.1 | length 36
  Top w0.2: R7.2 11.25,41.75 12.6,43.1 12.9,43.1 ; U17.1 13.1,42.9 12.9,43.1 ; v1(15.3,43.8) 15.1,44 13.3,44 12.9,43.6 12.9,43.1 ; J1.1@17.5,49.3 17.5,48.6 18.1,48 v1(18.2,48)
  Bottom w0.2: RTC1.5 17.53,33.25 18.7,34.42 18.7,37.602 18.202,38.1 17.5,38.1 15.4,36 13.4,36 12.9,36.5 12.9,38.5 14.4,40 14.4,42.4 14.9,42.9 14.9,43.4 v1(15.3,43.8) 16.4,44.9 16.9,44.9 17.5,45.5 17.5,47.3 v1(18.2,48) TP1.P$1
VDD-BKP: C1.2 C2.2 C3.2 C4.2 C5.1 J1.8 J2.2 MCU1.10 MCU1.38 R3.1 R4.1 R5.1 R6.1 RTC1.13 U1.6 U2.6 U3.6 U4.6 U5.6 U6.6 U7.6 U8.6 U9.6 U10.6 U11.6 U12.6 U13.6 U14.6 U15.6 U16.6 U17.6 | length 262.7
  Top w0.2: U2.6@1.5,42.8 1.3,42.8 1.2,42.7 1.2,40.7 1.8,40.1 2.7,40.1 v1(3.4,39.4) ; C3.2 3.8,11.5 v1(4.3,11) 4.6,10.7 4.6,8.898 4.1,8.398 4.1,7.7 v1(3.8,7.4) 3.8,6.6 3.6,6.4 U6.6 ; U5.6 3.4,23 3.6,22.8 6,22.8 6.4,23.2 6.4,24.2 v1(5.9,24.7) ; U4.6 4.8,30.4 5,30.6 5,31.2 5.6,31.8 v1(5.6,32.4) ; U3.6 5,36 5.7,36.7 v1(5.7,37.1) ; U1.6 5.8,43.1 5.7,43 5.7,41.4 5.9,41.2 v1(6.9,41.2) ; v1(7.6,20.4) 8.5,19.5 9.5,19.5 9.7,19.3 9.7,17.8 9.1,17.2 U8.6 ; U7.6 9.1,6.4 9.4,6.7 v1(9.4,7.3) ; v1(9,30.3) v1(10.4,30.3) 10.4,30.113 10.863,29.65 MCU1.10 ; v1(10.3,3.8) 13.2,3.8 13.9,3.1 14.8,3.1 16.1,1.8 16.1,1.2 16.5,0.8 17.7,0.8 18.3,1.4 18.3,2.3 ; U17.6 13.9,40.8 14.1,40.6 15.3,40.6 15.7,40.2 16.7,40.2 17.2,40.7 17.2,42.498 16.7,42.998 v1(16.7,44.2) 16.5,44.4 J1.8 ; U9.6 15.1,5.4 15.4,5.7 15.4,6.2 v1(15.1,6.5) ; U12.6 17.5,15.9 18.1,15.3 18.1,14.2 18.5,13.8 v1(19.5,13.8) ; v1(17.1,20.2) 17.4,20.5 18.3,20.5 18.6,20.2 U13.6 ; v1(17.5,4.398) 18.1,3.798 18.1,2.8 18.3,2.6 18.3,2.3 ; U16.6 18.5,41.1 18.4,41 18.4,39.3 v1(19.1,38.6) ; MCU1.38@20.237,29.15 21.037,29.15 21.294,29.406 v1(21.3,29.4) ; v1(20.9,20.6) 21.3,20.6 22.5,21.8 U14.6 ; v1(21.1,3.1) 20.3,2.3 18.3,2.3 ; U10.6 21.5,5.6 v1(21.5,6.3) ; v1(21.5,44.2) C1.2 ; v1(21.8,35.4) 22,35.6 22,39.8 22.5,40.3 22.5,41 v1(22.7,41.2) 22.7,41.8 22.8,41.9 U15.6 ; v1(24.2,24.5) 24.2,25.7 25.04,26.54 J2.2 ; U11.6 24.5,16.4 24.8,16.7 v1(24.8,17.1)
  Bottom w0.2: v1(3.8,7.4) 4.1,7.1 4.1,4.6 5.6,3.1 8.9,3.1 9.6,3.8 ; v1(4.3,11) 4.8,11.5 4.8,20.4 ; v1(6.9,41.2) 6.9,40.7 5.6,39.4 v1(3.4,39.4) 4.1,39.4 4.1,37.8 4.8,37.1 v1(5.7,37.1) 6.2,36.6 6.2,36.1 5.5,35.4 5.5,34.2 ; C2.2 C2.2@7.15,23.45 ; v1(7.6,20.4) 4.8,20.4 ; v1(9.4,7.3) 9.6,7.1 9.6,3.8 ; v1(10.3,3.8) 9.6,3.8 ; v1(10.4,30.3) 10.7,30.6 11.85,30.6 C5.1 11.95,30.6 12.72,30.6 13.21,31.09 ; R4.1 R3.1 13.6,30.7 13.21,31.09 ; C4.2@14.05,11.6 14.35,11.9 15.3,11.9 17.9,9.3 ; RTC1.13 13.87,31.75 13.21,31.09 ; v1(15.1,6.5) 14.8,6.2 14.8,5.1 15.902,3.998 17.1,3.998 v1(17.5,4.398) 17.9,4.798 17.9,9.3 ; v1(17.1,20.2) 17.7,19.6 20.7,19.6 20.9,19.8 v1(20.9,20.6) 20.9,22.602 21.898,23.6 23.3,23.6 v1(24.2,24.5) ; v1(19.1,38.6) 18.8,38.9 16,38.9 14.8,40.1 14.8,42.3 v1(16.7,44.2) 17.5,45 20.7,45 v1(21.5,44.2) 22.7,43 v1(22.7,41.2) ; v1(19.5,13.8) 20.6,13.8 21.3,14.5 ; R6.1 20.6,32.8 21.3,33.5 22.4,33.5 ; R5.1 21.5,35.7 v1(21.8,35.4) 22.4,34.8 22.4,33.5 ; v1(21.1,3.1) 21.5,3.5 v1(21.5,6.3) ; v1(24.8,17.1) 24.8,16.3 24,15.5 22.6,15.5 22.2,15.9 21.7,15.9 21.3,15.5 21.3,14.5 ; J2.2 26.16,26.54 23.6,29.1 21.6,29.1 v1(21.3,29.4) 20.8,29.9 20.8,30.5 ; 4.8,20.4 4.8,21.1 C2.2@7.15,23.45 ; 5.5,34.2 6.6,34.2 9,31.8 v1(9,30.3) 9,29.4 9.6,28.8 10.202,28.8 11,28.002 11,27.1 11.8,26.3 14.605,26.3 15.6,27.295 15.6,28.4 16.3,29.1 18.7,29.1 20.1,30.5 20.8,30.5 ; 5.5,34.2 5.5,32.5 v1(5.6,32.4) 5.7,32.3 5.7,26.9 6.5,26.1 6.5,25.3 v1(5.9,24.7) C2.2@7.15,23.45 ; 17.9,9.3 19.8,9.3 20.5,10 21.4,10 21.7,10.3 21.7,11.4 22.6,12.3 24.3,12.3 24.6,12.6 24.6,14.2 24.3,14.5 21.3,14.5 ; 20.8,30.5 20.8,31.2 21.2,31.6 22.9,31.6 23.3,32 23.3,32.6 22.4,33.5
VEH-SW: MCU1.54 U17.5 | length 8.5
  Top w0.2: U17.5 13.5,40.6 13.9,40.2 15.2,40.2 17.2,38.2 17.2,35.7 17.05,35.55 MCU1.54
VSYS-SW: MCU1.55 U17.4 | length 8.6
  Top w0.2: U17.4 13.1,40.5 13.8,39.8 15.1,39.8 16.8,38.1 16.8,35.9 16.55,35.65 MCU1.55
pads on no net: FD1.1 FD2.1 FD3.1 FD4.1 J1.6 J1.7 J1.9 J1.10 J2.6 MCU1.8 MCU1.27 MCU1.28 MCU1.29 MCU1.30 MCU1.31 MCU1.32 MCU1.33 MCU1.34 MCU1.35 MCU1.36 MCU1.39 MCU1.40 MCU1.47 RTC1.1 RTC1.8 RTC1.12 RTC1.15 RTC1.16 U16.9 U17.3 U17.7

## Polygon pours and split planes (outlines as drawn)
GND on Top "Polygon_1_Net_GND" (solid, remove dead copper, pour order 1): -0.127,-0.127 26.627,-0.127 26.627,50.627 -0.127,50.627
GND on Bottom "Polygon_2_Net_GND" (solid, remove dead copper, pour order 0): -0.127,-0.127 26.627,-0.127 26.627,50.627 -0.127,50.627

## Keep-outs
Top:
  region: 11,0 cw(c12.8,0) 12.8,1.8 cw(c12.8,0) 14.6,0 11,0
  region: 26.5,7.2 cw(c26.5,9) 24.7,9 cw(c26.5,9) 26.5,10.8 26.5,7.2
  region: 7.8,48.5 cw(c6,48.5) 6,46.7 cw(c6,48.5) 4.2,48.5 7.8,48.5
Bottom:
  region: 7.8,48.5 cw(c6,48.5) 6,46.7 cw(c6,48.5) 4.2,48.5 7.8,48.5
  region: 26.5,7.2 cw(c26.5,9) 24.7,9 cw(c26.5,9) 26.5,10.8 26.5,7.2
  region: 11,0 cw(c12.8,0) 12.8,1.8 cw(c12.8,0) 14.6,0 11,0
Keep-Out Layer:
  the board outline again, w0

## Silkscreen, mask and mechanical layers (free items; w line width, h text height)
Top Overlay:
  text "v1.2" at 15.348,21.093 h1.08 r90
  text "BESt" at 13.54,16.816 h1.21 r90
  text "module" at 11.407,15.507 h1.21 r90
Dimension:
  the board outline again, w0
